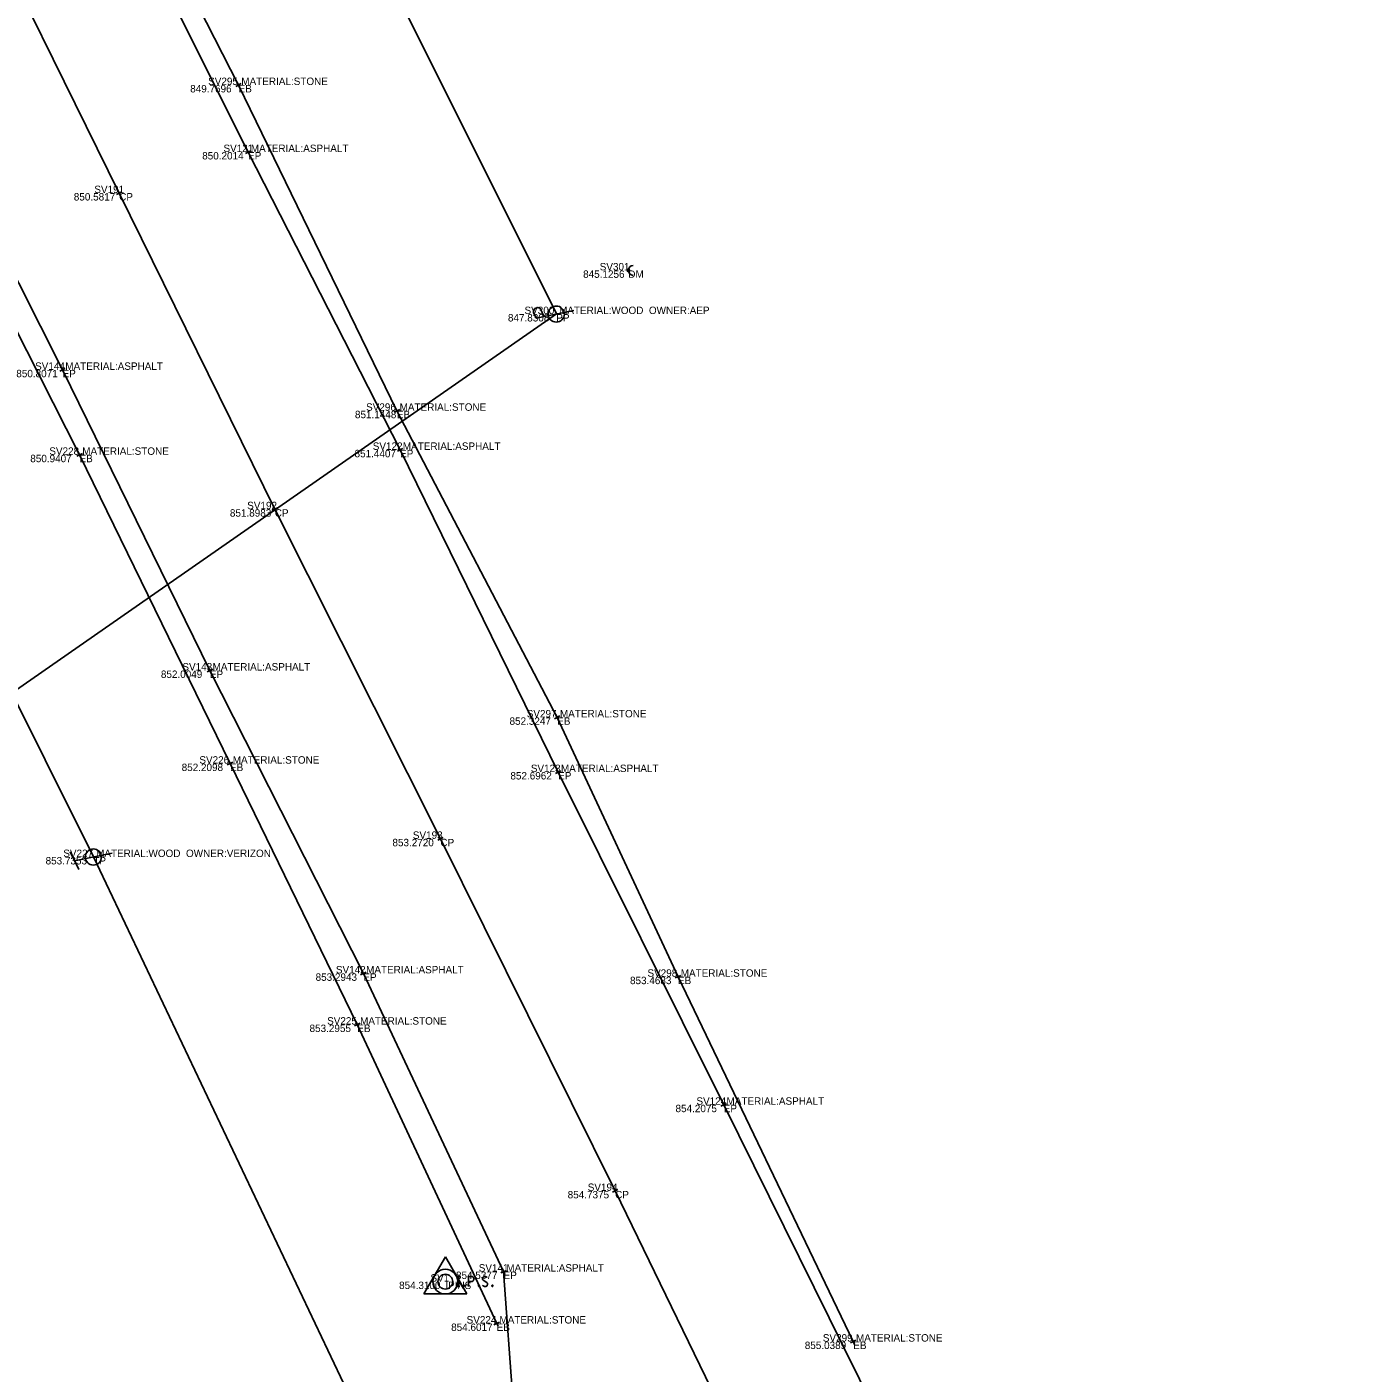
# Model space of a CAD drawing. Extents: x 1715717 to 1717046, y 393954 to 396000.
# Drawn here: x 1716452.6 to 1716560.8, y 394169.3 to 394278.1 of the extents above; entities that cross this region are included whole.
import ezdxf

# ---------------------------------------------------------------- set-up
doc = ezdxf.new("R2010")
doc.units = 0
for name, color, linetype in [('PV_X_COP', 7, 'Continuous'), ('PV_X_EOP', 7, 'Continuous'), ('PV_X_Shoulder', 7, 'Continuous'), ('SV_Control_Point', 7, 'Continuous'), ('SV_P_Mon_Cells_Set', 7, 'Continuous'), ('SV_X_Shot_Marker', 7, 'Continuous'), ('SV_X_Text_Comment', 7, 'Continuous'), ('SV_X_Text_Description', 7, 'Continuous'), ('SV_X_Text_Elevation', 7, 'Continuous'), ('SV_X_Text_Name', 7, 'Continuous'), ('UT_X_Electric_Cells', 7, 'Continuous'), ('UT_X_Misc_Cells', 7, 'Continuous'), ('UT_X_Overhead_Electric', 7, 'Continuous'), ('UT_X_Overhead_Telecom', 7, 'Continuous'), ('UT_X_Telecom_Cells', 7, 'Continuous')]:
    doc.layers.add(name, color=color, linetype=linetype)

msp = doc.modelspace()

# ---------------------------------------------------------------- linework, layer by layer
at = {"layer": 'PV_X_COP'}
msp.add_lwpolyline([(1716316.41, 394551.83), (1716329.98, 394525.07), (1716342.64, 394500.7), (1716355.43, 394474.91), (1716368.06, 394449.35), (1716381.47, 394422.5), (1716394.06, 394396.97), (1716407.48, 394370.48), (1716421.67, 394341.9), (1716435.06, 394315.11), (1716447.6, 394290.07), (1716460.11, 394264.71), (1716472.69, 394239.15), (1716486.08, 394212.5), (1716500.21, 394184.03), (1716512.53, 394158.68), (1716522.87, 394138.69), (1716535.3, 394112.62), (1716550.33, 394081.5)], dxfattribs=at)
at = {"layer": 'PV_X_EOP'}
for p, q in [((1716455.53, 394250.42), (1716442.46, 394276.28)), ((1716467.44, 394226.11), (1716455.53, 394250.42)), ((1716479.85, 394201.62), (1716467.44, 394226.11)), ((1716491.19, 394177.51), (1716479.85, 394201.62)), ((1716491.97, 394166.76), (1716491.19, 394177.51))]:
    msp.add_line(p, q, dxfattribs=at)
msp.add_lwpolyline([(1716325.75, 394558.4), (1716339.31, 394531.89), (1716352.49, 394505.72), (1716365.43, 394479.6), (1716378.65, 394453.38), (1716392.13, 394426.2), (1716405.28, 394399.09), (1716418.42, 394372.49), (1716430.72, 394347.4), (1716443.91, 394321), (1716457.06, 394294.96), (1716470.53, 394268.03), (1716482.82, 394243.95), (1716495.6, 394217.9), (1716508.99, 394191), (1716522.38, 394163.92), (1716535.04, 394138.11), (1716548.85, 394110.2), (1716560.84, 394086.42)], dxfattribs=at)
at = {"layer": 'PV_X_Shoulder'}
for points in [[(1716326.15, 394561.27), (1716340.2, 394533.81), (1716352.99, 394507.82), (1716366.47, 394482.2), (1716379.27, 394455.43), (1716392.58, 394429.7), (1716405.35, 394404.37), (1716417.24, 394378.92), (1716430.47, 394351.93), (1716443.77, 394325.47), (1716457.4, 394297.65), (1716469.76, 394273.45), (1716482.56, 394247.11), (1716495.52, 394222.32), (1716505.29, 394201.35), (1716519.46, 394171.85)], [(1716490.63, 394173.31), (1716479.36, 394197.48), (1716469.07, 394218.58), (1716456.9, 394243.55), (1716445.15, 394266.71), (1716436.35, 394285.17), (1716429.55, 394299.1)]]:
    msp.add_lwpolyline(points, dxfattribs=at)
at = {"layer": 'SV_Control_Point'}
for p, q in [((1716484.75, 394175.7), (1716486.48, 394178.7)), ((1716486.48, 394178.7), (1716488.21, 394175.7)), ((1716486.48, 394176.7), (1716486.48, 394176.7)), ((1716488.21, 394175.7), (1716484.75, 394175.7))]:
    msp.add_line(p, q, dxfattribs=at)
msp.add_circle((1716486.48, 394176.7), 1, dxfattribs=at)
at = {"layer": 'SV_P_Mon_Cells_Set'}
for points in [[(1716487.49, 394177.1), (1716487.66, 394177.1)], [(1716487.58, 394176.3), (1716487.58, 394177.1)], [(1716488.36, 394176.3), (1716488.36, 394177.1), (1716488.62, 394177.1), (1716488.65, 394177.1), (1716488.69, 394177.08), (1716488.71, 394177.07), (1716488.72, 394177.06), (1716488.75, 394177.03), (1716488.76, 394177), (1716488.77, 394176.95), (1716488.77, 394176.87), (1716488.77, 394176.85), (1716488.76, 394176.81), (1716488.73, 394176.76), (1716488.71, 394176.74), (1716488.7, 394176.73), (1716488.67, 394176.72), (1716488.62, 394176.71), (1716488.36, 394176.71)], [(1716489.86, 394177.05), (1716489.85, 394177.06), (1716489.84, 394177.07), (1716489.79, 394177.09), (1716489.73, 394177.1), (1716489.68, 394177.1), (1716489.67, 394177.1), (1716489.59, 394177.08), (1716489.53, 394177.05), (1716489.49, 394177), (1716489.48, 394176.95), (1716489.48, 394176.91), (1716489.49, 394176.86), (1716489.54, 394176.81), (1716489.84, 394176.63), (1716489.87, 394176.6), (1716489.88, 394176.57), (1716489.89, 394176.54), (1716489.89, 394176.5), (1716489.89, 394176.46), (1716489.88, 394176.44), (1716489.87, 394176.4), (1716489.86, 394176.38), (1716489.85, 394176.36), (1716489.83, 394176.34), (1716489.81, 394176.33), (1716489.79, 394176.32), (1716489.78, 394176.31), (1716489.73, 394176.3), (1716489.65, 394176.3), (1716489.6, 394176.32), (1716489.53, 394176.36), (1716489.48, 394176.4)], [(1716487.49, 394176.3), (1716487.66, 394176.3)], [(1716488.06, 394176.41), (1716488.08, 394176.41), (1716488.1, 394176.4), (1716488.12, 394176.37), (1716488.12, 394176.34), (1716488.1, 394176.32), (1716488.08, 394176.3), (1716488.06, 394176.3), (1716488.04, 394176.32), (1716488.02, 394176.34), (1716488.02, 394176.37), (1716488.04, 394176.4), (1716488.06, 394176.41)], [(1716489.18, 394176.41), (1716489.21, 394176.41), (1716489.22, 394176.4), (1716489.24, 394176.37), (1716489.24, 394176.34), (1716489.22, 394176.32), (1716489.21, 394176.3), (1716489.18, 394176.3), (1716489.16, 394176.32), (1716489.15, 394176.34), (1716489.15, 394176.37), (1716489.16, 394176.4), (1716489.18, 394176.41)], [(1716490.27, 394176.41), (1716490.3, 394176.41), (1716490.32, 394176.4), (1716490.33, 394176.37), (1716490.33, 394176.34), (1716490.32, 394176.32), (1716490.3, 394176.3), (1716490.27, 394176.3), (1716490.26, 394176.32), (1716490.24, 394176.34), (1716490.24, 394176.37), (1716490.26, 394176.4), (1716490.27, 394176.41)]]:
    msp.add_lwpolyline(points, dxfattribs=at)
msp.add_circle((1716486.48, 394176.7), 0.6, dxfattribs=at)
at = {"layer": 'SV_X_Shot_Marker'}
for p, q in [((1716469.98, 394273.56), (1716469.54, 394273.33)), ((1716469.64, 394273.67), (1716469.87, 394273.23)), ((1716469.76, 394273.45), (1716469.76, 394273.45)), ((1716470.76, 394268.14), (1716470.31, 394267.91)), ((1716470.42, 394268.25), (1716470.65, 394267.8)), ((1716470.53, 394268.03), (1716470.53, 394268.03)), ((1716460.33, 394264.82), (1716459.89, 394264.6)), ((1716460, 394264.94), (1716460.22, 394264.49)), ((1716460.11, 394264.71), (1716460.11, 394264.71)), ((1716455.3, 394250.31), (1716455.75, 394250.53)), ((1716455.64, 394250.2), (1716455.41, 394250.64)), ((1716455.53, 394250.42), (1716455.53, 394250.42)), ((1716482.79, 394247.22), (1716482.34, 394247)), ((1716482.45, 394247.34), (1716482.67, 394246.89)), ((1716482.56, 394247.11), (1716482.56, 394247.11)), ((1716456.68, 394243.44), (1716457.13, 394243.66)), ((1716457.01, 394243.33), (1716456.79, 394243.78)), ((1716456.9, 394243.55), (1716456.9, 394243.55)), ((1716483.04, 394244.06), (1716482.6, 394243.84)), ((1716482.71, 394244.17), (1716482.93, 394243.73)), ((1716482.82, 394243.95), (1716482.82, 394243.95)), ((1716472.91, 394239.26), (1716472.46, 394239.04)), ((1716472.58, 394239.37), (1716472.8, 394238.92)), ((1716472.69, 394239.15), (1716472.69, 394239.15)), ((1716467.22, 394226), (1716467.67, 394226.22)), ((1716467.55, 394225.88), (1716467.33, 394226.33)), ((1716467.44, 394226.11), (1716467.44, 394226.11)), ((1716495.74, 394222.44), (1716495.3, 394222.2)), ((1716495.4, 394222.54), (1716495.63, 394222.1)), ((1716495.52, 394222.32), (1716495.52, 394222.32)), ((1716468.84, 394218.47), (1716469.29, 394218.69)), ((1716469.18, 394218.35), (1716468.96, 394218.8)), ((1716469.07, 394218.58), (1716469.07, 394218.58)), ((1716495.83, 394218.01), (1716495.38, 394217.79)), ((1716495.49, 394218.12), (1716495.71, 394217.67)), ((1716495.6, 394217.9), (1716495.6, 394217.9)), ((1716486.31, 394212.61), (1716485.86, 394212.38)), ((1716485.97, 394212.72), (1716486.2, 394212.27)), ((1716486.08, 394212.5), (1716486.08, 394212.5)), ((1716479.63, 394201.5), (1716480.08, 394201.73)), ((1716479.97, 394201.39), (1716479.74, 394201.84)), ((1716479.85, 394201.62), (1716479.85, 394201.62)), ((1716505.51, 394201.46), (1716505.06, 394201.25)), ((1716505.18, 394201.58), (1716505.39, 394201.13)), ((1716505.29, 394201.35), (1716505.29, 394201.35)), ((1716479.14, 394197.38), (1716479.59, 394197.59)), ((1716479.47, 394197.26), (1716479.26, 394197.71)), ((1716479.36, 394197.48), (1716479.36, 394197.48)), ((1716509.21, 394191.11), (1716508.76, 394190.89)), ((1716508.87, 394191.22), (1716509.1, 394190.77)), ((1716508.99, 394191), (1716508.99, 394191)), ((1716500.43, 394184.14), (1716499.99, 394183.92)), ((1716500.1, 394184.26), (1716500.32, 394183.81)), ((1716500.21, 394184.03), (1716500.21, 394184.03)), ((1716490.97, 394177.4), (1716491.42, 394177.61)), ((1716491.3, 394177.28), (1716491.09, 394177.73)), ((1716491.19, 394177.51), (1716491.19, 394177.51)), ((1716490.4, 394173.21), (1716490.86, 394173.42)), ((1716490.74, 394173.09), (1716490.53, 394173.54)), ((1716490.63, 394173.31), (1716490.63, 394173.31)), ((1716519.68, 394171.96), (1716519.23, 394171.74)), ((1716519.35, 394172.07), (1716519.56, 394171.62)), ((1716519.46, 394171.85), (1716519.46, 394171.85))]:
    msp.add_line(p, q, dxfattribs=at)
at = {"layer": 'UT_X_Electric_Cells'}
for p, q in [((1716493.83, 394254.61), (1716496.88, 394255.21)), ((1716494.48, 394254.73), (1716494.21, 394255.27)), ((1716493.83, 394254.61), (1716493.64, 394254.99))]:
    msp.add_line(p, q, dxfattribs=at)
msp.add_circle((1716495.45, 394254.93), 0.65, dxfattribs=at)
msp.add_arc((1716493.93, 394255.13), 0.319, 25.1605, 207.4071, dxfattribs=at)
at = {"layer": 'UT_X_Misc_Cells'}
msp.add_circle((1716501.27, 394258.46), 0.1, dxfattribs=at)
msp.add_arc((1716501.67, 394258.46), 0.4, 90, 270, dxfattribs=at)
at = {"layer": 'UT_X_Overhead_Electric'}
for p, q in [((1716495.47, 394254.94), (1716355.28, 394535.61)), ((1716326.79, 394137.58), (1716495.47, 394254.94))]:
    msp.add_line(p, q, dxfattribs=at)
at = {"layer": 'UT_X_Overhead_Telecom'}
for p, q in [((1716377.83, 394371.81), (1716458.03, 394211.04)), ((1716458.03, 394211.04), (1716504.84, 394112.54))]:
    msp.add_line(p, q, dxfattribs=at)
at = {"layer": 'UT_X_Telecom_Cells'}
for p, q in [((1716456.15, 394211.44), (1716456.85, 394210.01)), ((1716456.5, 394210.73), (1716459.55, 394211.33))]:
    msp.add_line(p, q, dxfattribs=at)
msp.add_circle((1716458.02, 394211.03), 0.65, dxfattribs=at)

# ---------------------------------------------------------------- texts
at = {"layer": 'SV_X_Text_Comment'}
for s, p in [('EB', (1716469.76, 394272.85)), ('EP', (1716470.53, 394267.43)), ('CP', (1716460.11, 394264.11)), ('DM', (1716501.27, 394257.86)), ('PP', (1716495.45, 394254.33)), ('EP', (1716455.53, 394249.82)), ('EB', (1716482.56, 394246.51)), ('EB', (1716456.9, 394242.95)), ('EP', (1716482.82, 394243.35)), ('CP', (1716472.69, 394238.55)), ('EP', (1716467.44, 394225.51)), ('EB', (1716495.52, 394221.72)), ('EB', (1716469.07, 394217.98)), ('EP', (1716495.6, 394217.3)), ('CP', (1716486.08, 394211.9)), ('TP', (1716458.02, 394210.43)), ('EP', (1716479.85, 394201.02)), ('EB', (1716505.29, 394200.75)), ('EB', (1716479.36, 394196.88)), ('EP', (1716508.99, 394190.4)), ('CP', (1716500.21, 394183.43)), ('EP', (1716491.19, 394176.91)), ('IPINS', (1716486.48, 394176.1)), ('EB', (1716490.63, 394172.71)), ('EB', (1716519.46, 394171.25))]:
    msp.add_text(s, height=0.6, dxfattribs=at).set_placement(p)
at = {"layer": 'SV_X_Text_Description'}
for s, p in [(' MATERIAL:STONE ', (1716469.76, 394273.45)), (' MATERIAL:ASPHALT ', (1716470.53, 394268.03)), (' MATERIAL:WOOD  OWNER:AEP ', (1716495.45, 394254.93)), (' MATERIAL:ASPHALT ', (1716455.53, 394250.42)), (' MATERIAL:STONE ', (1716482.56, 394247.11)), (' MATERIAL:ASPHALT ', (1716482.82, 394243.95)), (' MATERIAL:STONE ', (1716456.9, 394243.55)), (' MATERIAL:ASPHALT ', (1716467.44, 394226.11)), (' MATERIAL:STONE ', (1716495.52, 394222.32)), (' MATERIAL:STONE ', (1716469.07, 394218.58)), (' MATERIAL:ASPHALT ', (1716495.6, 394217.9)), (' MATERIAL:WOOD  OWNER:VERIZON ', (1716458.02, 394211.03)), (' MATERIAL:ASPHALT ', (1716479.85, 394201.62)), (' MATERIAL:STONE ', (1716505.29, 394201.35)), (' MATERIAL:STONE ', (1716479.36, 394197.48)), (' MATERIAL:ASPHALT ', (1716508.99, 394191)), (' MATERIAL:ASPHALT ', (1716491.19, 394177.51)), (' MATERIAL:STONE ', (1716490.63, 394173.31)), (' MATERIAL:STONE ', (1716519.46, 394171.85))]:
    msp.add_text(s, height=0.6, dxfattribs=at).set_placement(p)
at = {"layer": 'SV_X_Text_Elevation'}
for s, p in [('849.7696', (1716465.85, 394272.85)), ('850.2014', (1716466.82, 394267.43)), ('850.5817', (1716456.44, 394264.11)), ('845.1256', (1716497.62, 394257.86)), ('847.8308', (1716491.54, 394254.33)), ('850.8071', (1716451.79, 394249.82)), ('851.1448', (1716479.17, 394246.51)), ('850.9407', (1716452.92, 394242.95)), ('851.4407', (1716479.14, 394243.35)), ('851.8983', (1716469.06, 394238.55)), ('852.0049', (1716463.48, 394225.51)), ('852.3247', (1716491.67, 394221.72)), ('852.2098', (1716465.16, 394217.98)), ('852.6962', (1716491.74, 394217.3)), ('853.2720', (1716482.2, 394211.9)), ('853.7353', (1716454.16, 394210.43)), ('853.2943', (1716475.99, 394201.02)), ('853.4683', (1716501.41, 394200.75)), ('853.2955', (1716475.5, 394196.88)), ('854.2075', (1716505.09, 394190.4)), ('854.7375', (1716496.37, 394183.43)), ('854.5377', (1716487.34, 394176.91)), ('854.3100', (1716482.74, 394176.1)), ('854.6017', (1716486.95, 394172.71)), ('855.0389', (1716515.54, 394171.25))]:
    msp.add_text(s, height=0.6, dxfattribs=at).set_placement(p)
at = {"layer": 'SV_X_Text_Name'}
for s, p in [('SV295', (1716467.3, 394273.45)), ('SV121', (1716468.54, 394268.03)), ('SV191', (1716458.1, 394264.71)), ('SV301', (1716498.96, 394258.46)), ('SV300', (1716492.88, 394254.93)), ('SV144', (1716453.31, 394250.42)), ('SV296', (1716480.07, 394247.11)), ('SV122', (1716480.61, 394243.95)), ('SV228', (1716454.46, 394243.55)), ('SV192', (1716470.46, 394239.15)), ('SV143', (1716465.22, 394226.11)), ('SV297', (1716493.06, 394222.32)), ('SV226', (1716466.59, 394218.58)), ('SV123', (1716493.39, 394217.9)), ('SV193', (1716483.85, 394212.5)), ('SV227', (1716455.59, 394211.03)), ('SV142', (1716477.63, 394201.62)), ('SV298', (1716502.82, 394201.35)), ('SV225', (1716476.92, 394197.48)), ('SV124', (1716506.78, 394191)), ('SV194', (1716497.99, 394184.03)), ('SV141', (1716489.18, 394177.51)), ('SV1', (1716485.28, 394176.7)), ('SV224', (1716488.2, 394173.31)), ('SV299', (1716517, 394171.85))]:
    msp.add_text(s, height=0.6, dxfattribs=at).set_placement(p)

doc.saveas('drawing.dxf')
